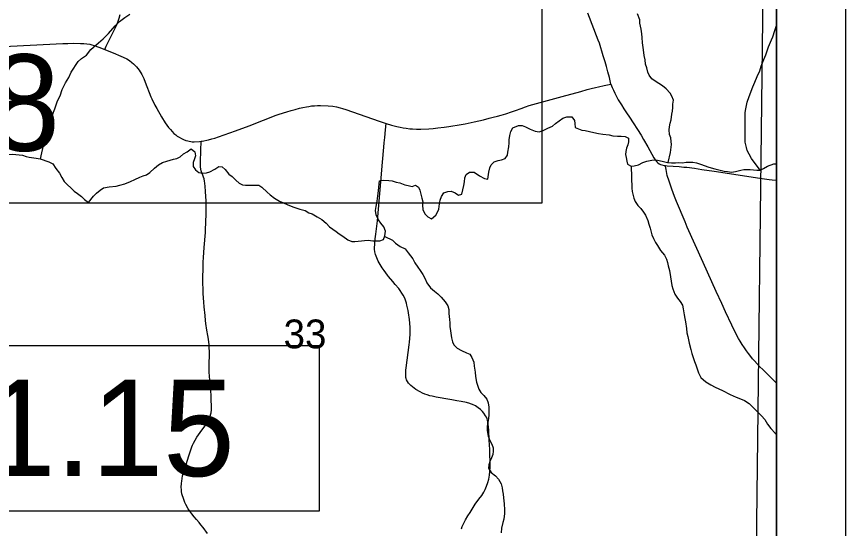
# Model space of a CAD drawing. Extents: x 0 to 34, y 0 to 22.
# Drawn here: x 24.295 to 25.5, y 16.628 to 17.371 of the extents above; entities that cross this region are included whole.
import ezdxf

# ---------------------------------------------------------------- set-up
doc = ezdxf.new("R2010")
doc.units = 0
for name, color, linetype in [('GM_X_Corporation', 7, 'Continuous'), ('GM_X_County_Road', 7, 'Continuous'), ('GM_X_Minor_River', 7, 'Continuous'), ('GM_X_Section_Text', 7, 'Continuous'), ('GM_X_Township_Road', 7, 'Continuous'), ('SH_Data', 7, 'Continuous'), ('SH_Text', 7, 'Continuous')]:
    doc.layers.add(name, color=color, linetype=linetype)

msp = doc.modelspace()

# ---------------------------------------------------------------- linework, layer by layer
at = {"layer": 'GM_X_Corporation'}
msp.add_lwpolyline([(25.4, 14.4307), (25.4, 19.0068), (24.5766, 19.0222), (24.3186, 19.0261), (24.3186, 19.1409), (24.169, 19.1418), (23.786, 19.1434), (23.5499, 19.1465), (23.3329, 19.1508), (22.6423, 19.1645), (21.8956, 19.1793), (21.7744, 19.1817), (21.5297, 19.1865), (21.2652, 19.1913), (20.8916, 19.1966), (20.254, 19.2058), (20.2471, 18.8539), (20.2208, 16.9558), (20.1987, 15.2691)], dxfattribs=at)
for points in [[(24.2765, 17.4936), (25.3807, 17.4896), (25.3688, 16.474), (24.2658, 16.4792), (24.2698, 16.6327)], [(25.4, 16.4736), (25.4, 17.4893), (25.3807, 17.4896), (25.3688, 16.474)]]:
    msp.add_lwpolyline(points, close=True, dxfattribs=at)
at = {"layer": 'GM_X_County_Road'}
for points in [[(25.1592, 17.2732), (25.158, 17.2779), (25.1569, 17.2826), (25.1547, 17.2912), (25.1526, 17.2989), (25.1507, 17.3055), (25.148, 17.3143), (25.1424, 17.3325), (25.1408, 17.3369), (25.1255, 17.3762)], [(24.2671, 17.3274), (24.3623, 17.332), (24.3697, 17.3322), (24.3776, 17.3325), (24.3882, 17.3323), (24.3932, 17.3321), (24.3971, 17.3316), (24.4017, 17.331), (24.4047, 17.3303), (24.4078, 17.3293), (24.415, 17.3267), (24.4233, 17.3233), (24.4392, 17.3171), (24.4432, 17.3154), (24.4503, 17.3124), (24.4553, 17.3098), (24.4594, 17.3073), (24.4626, 17.3047), (24.4653, 17.3024), (24.4676, 17.3003), (24.4695, 17.2983), (24.4714, 17.2959), (24.4733, 17.2933), (24.4773, 17.287), (24.4782, 17.2853), (24.48, 17.2812), (24.4821, 17.2759), (24.4902, 17.2549), (24.4917, 17.2517), (24.4962, 17.2424), (24.4989, 17.2375), (24.5058, 17.2258), (24.5113, 17.217), (24.5137, 17.2136), (24.5161, 17.2103), (24.519, 17.207), (24.5216, 17.2041), (24.524, 17.2016), (24.5265, 17.1994), (24.5288, 17.1977), (24.5316, 17.1959), (24.535, 17.1939), (24.5379, 17.1925), (24.541, 17.1914), (24.5441, 17.1906), (24.5503, 17.1895), (24.5531, 17.1893), (24.5612, 17.1897), (24.5635, 17.1901), (24.5649, 17.1903), (24.574, 17.1923), (24.5789, 17.1935), (24.5834, 17.1948), (24.5888, 17.1966), (24.6133, 17.2051), (24.6331, 17.2126), (24.6542, 17.2208), (24.6629, 17.2242), (24.6712, 17.2275), (24.6767, 17.2294), (24.6882, 17.2331), (24.6945, 17.235), (24.7, 17.2364), (24.7065, 17.238), (24.7114, 17.2392), (24.7166, 17.2401), (24.7202, 17.2408), (24.7241, 17.2414), (24.7281, 17.2418), (24.7325, 17.242), (24.7368, 17.2422), (24.7483, 17.2418), (24.755, 17.2409), (24.7602, 17.24), (24.7656, 17.2386), (24.7689, 17.2377), (24.7737, 17.2362), (24.8222, 17.2194), (24.8323, 17.216), (24.8402, 17.2137), (24.8478, 17.2117), (24.853, 17.2106), (24.8573, 17.2097), (24.8616, 17.209), (24.8667, 17.2084), (24.8707, 17.2081), (24.8763, 17.2078), (24.8827, 17.2077), (24.8943, 17.2081), (24.9008, 17.2086), (24.9077, 17.2094), (24.9167, 17.2105), (24.9236, 17.2115), (24.9291, 17.2124), (24.9354, 17.2134), (24.9474, 17.2156), (24.9603, 17.2183), (24.9737, 17.2214), (24.9821, 17.2235), (24.9881, 17.2249), (24.9941, 17.2264), (24.9995, 17.2279), (25.0064, 17.2301), (25.0146, 17.2329), (25.0205, 17.2349), (25.0286, 17.2379), (25.0348, 17.2401), (25.0401, 17.2419), (25.0455, 17.2437), (25.0882, 17.2551), (25.1153, 17.2626), (25.1247, 17.2652), (25.1305, 17.2667), (25.1366, 17.2682), (25.141, 17.2692), (25.1494, 17.271), (25.1592, 17.2732)], [(25.1592, 17.2732), (25.1611, 17.2684), (25.1627, 17.2645), (25.1647, 17.2601), (25.1672, 17.2553), (25.1699, 17.2501), (25.1743, 17.2431), (25.178, 17.2372), (25.1816, 17.2314), (25.186, 17.2249), (25.2029, 17.1988), (25.2067, 17.1926), (25.2127, 17.1822), (25.2217, 17.1661), (25.2236, 17.1629), (25.2257, 17.1602), (25.2271, 17.1588), (25.2294, 17.1572), (25.2313, 17.1564), (25.2329, 17.1558), (25.2367, 17.1549), (25.2385, 17.1547)], [(25.2385, 17.1547), (25.241, 17.1544), (25.2498, 17.1539), (25.2585, 17.1533), (25.2653, 17.1527), (25.2695, 17.1523), (25.2807, 17.1509), (25.2913, 17.1492), (25.3091, 17.1466), (25.3758, 17.1365), (25.3824, 17.1356), (25.3892, 17.1346), (25.3934, 17.1342), (25.4, 17.1338)], [(25.4, 16.8388), (25.3914, 16.8469), (25.3802, 16.8578), (25.375, 16.863), (25.3677, 16.871), (25.3651, 16.874), (25.3627, 16.8772), (25.3593, 16.8816), (25.3563, 16.8858), (25.3534, 16.8899), (25.3501, 16.8948), (25.3468, 16.8998), (25.3446, 16.9036), (25.3418, 16.9086), (25.3348, 16.9231), (25.3259, 16.9423), (25.3203, 16.9545), (25.3123, 16.9719), (25.2933, 17.0138), (25.2702, 17.0654), (25.2669, 17.0728), (25.2545, 17.1028), (25.2517, 17.1099), (25.2478, 17.1203), (25.2437, 17.1322), (25.241, 17.1406), (25.2404, 17.1433), (25.2392, 17.1493), (25.2386, 17.1538), (25.2385, 17.1547)]]:
    msp.add_lwpolyline(points, dxfattribs=at)
at = {"layer": 'GM_X_Minor_River'}
for points in [[(24.3298, 17.1643), (24.3311, 17.169), (24.3318, 17.1735), (24.3352, 17.1876), (24.3363, 17.1929), (24.3386, 17.2024), (24.342, 17.2134), (24.3431, 17.2184), (24.3465, 17.226), (24.3506, 17.2374), (24.3547, 17.2491), (24.3585, 17.256), (24.3615, 17.2651), (24.3664, 17.275), (24.371, 17.2826), (24.3747, 17.2906), (24.3849, 17.3058), (24.3898, 17.3103), (24.397, 17.3153), (24.4031, 17.3233), (24.4144, 17.3332), (24.4209, 17.3389), (24.4288, 17.3469), (24.4387, 17.3579), (24.4447, 17.364), (24.4527, 17.3701), (24.4599, 17.375)], [(25.2422, 17.1591), (25.2456, 17.1736), (25.2471, 17.1854), (25.2467, 17.19), (25.2463, 17.1949), (25.2444, 17.1998), (25.2436, 17.2067), (25.2444, 17.2112), (25.2451, 17.2165), (25.2466, 17.2215), (25.2477, 17.2295), (25.2485, 17.234), (25.2492, 17.239), (25.2492, 17.2439), (25.2499, 17.25), (25.2476, 17.2557), (25.2454, 17.2602), (25.2393, 17.2663), (25.2339, 17.2705), (25.2233, 17.2773), (25.2187, 17.2807), (25.2149, 17.286), (25.213, 17.2905), (25.2111, 17.2966), (25.2095, 17.3023), (25.2087, 17.3084), (25.2076, 17.3148), (25.2064, 17.3232), (25.2052, 17.3331), (25.2045, 17.3407), (25.2041, 17.3464), (25.2029, 17.3528), (25.2013, 17.3619), (25.201, 17.3665), (25.1979, 17.3752)], [(25.3761, 17.1481), (25.3637, 17.1651), (25.3603, 17.1715), (25.3572, 17.1765), (25.3561, 17.181), (25.3545, 17.189), (25.3541, 17.1977), (25.3545, 17.2027), (25.3544, 17.2179), (25.3541, 17.2228), (25.3544, 17.2319), (25.3551, 17.2372), (25.3574, 17.2467), (25.36, 17.2551), (25.3653, 17.2692), (25.3683, 17.276), (25.3717, 17.2844), (25.3755, 17.2923), (25.3777, 17.2992), (25.3815, 17.3087), (25.3841, 17.3159), (25.3882, 17.3273), (25.3924, 17.3376), (25.3946, 17.3421), (25.3973, 17.3512), (25.4, 17.3583)], [(24.8229, 17.1326), (24.8282, 17.1338), (24.8362, 17.133), (24.8411, 17.1327), (24.8472, 17.1308), (24.8521, 17.1296), (24.8597, 17.127), (24.8646, 17.1259), (24.87, 17.1244), (24.8749, 17.1263), (24.8795, 17.1236), (24.8814, 17.1191), (24.8829, 17.1134), (24.8845, 17.1073), (24.8856, 17.102), (24.8852, 17.0974), (24.8856, 17.091), (24.8887, 17.0849), (24.8929, 17.0803), (24.8982, 17.0773), (24.9047, 17.0826), (24.9088, 17.091), (24.9095, 17.0959), (24.911, 17.1043), (24.9129, 17.11), (24.9163, 17.1153), (24.922, 17.1172), (24.9269, 17.1176), (24.9326, 17.1153), (24.9376, 17.1116), (24.9425, 17.1131), (24.944, 17.1195), (24.9451, 17.1256), (24.9463, 17.1313), (24.947, 17.137), (24.9485, 17.1416), (24.9538, 17.1454), (24.9603, 17.145), (24.9682, 17.1397), (24.9755, 17.1359), (24.9804, 17.1352), (24.9815, 17.1451), (24.983, 17.1515), (24.9849, 17.1561), (24.9894, 17.1603), (24.9951, 17.1622), (25.0001, 17.1629), (25.0054, 17.1649), (25.0088, 17.1698), (25.0095, 17.1744), (25.0106, 17.182), (25.011, 17.1877), (25.0113, 17.1922), (25.0121, 17.1983), (25.0136, 17.2044), (25.0166, 17.2097), (25.0246, 17.2131), (25.0303, 17.2128), (25.0348, 17.2112), (25.0417, 17.2075), (25.0489, 17.2048), (25.055, 17.2037), (25.0607, 17.2056), (25.0675, 17.209), (25.0743, 17.2121), (25.0788, 17.2159), (25.0838, 17.2197), (25.0894, 17.2235), (25.0951, 17.2258), (25.1023, 17.2258), (25.1062, 17.2205), (25.1066, 17.2159), (25.1073, 17.2102), (25.1119, 17.208), (25.1168, 17.2064), (25.1218, 17.2057), (25.1282, 17.2042), (25.1343, 17.2027), (25.1411, 17.2015), (25.1472, 17.2004), (25.1567, 17.1993), (25.1617, 17.1982), (25.1685, 17.1974), (25.1742, 17.1974), (25.1799, 17.1971), (25.1845, 17.1948), (25.1849, 17.1895), (25.1837, 17.1849), (25.1818, 17.1803), (25.1807, 17.1754), (25.1804, 17.1708), (25.1811, 17.1663), (25.1823, 17.1614), (25.1834, 17.1568), (25.1884, 17.1538), (25.1929, 17.1542), (25.199, 17.1561), (25.2055, 17.1591), (25.2115, 17.1614), (25.2187, 17.1626), (25.2244, 17.1629)], [(24.1857, 17.2003), (24.1932, 17.1979), (24.1993, 17.1972), (24.2091, 17.1953), (24.2145, 17.1942), (24.2198, 17.1931), (24.2247, 17.1919), (24.2319, 17.1897), (24.2373, 17.1882), (24.2434, 17.184), (24.2483, 17.1794), (24.2567, 17.176), (24.2627, 17.1734), (24.2681, 17.1723), (24.2734, 17.1719), (24.2783, 17.1715), (24.2829, 17.1711), (24.2893, 17.1712), (24.2943, 17.1708), (24.2988, 17.1704), (24.3038, 17.1697), (24.3091, 17.1678), (24.3136, 17.167), (24.3239, 17.1655)], [(24.3239, 17.1655), (24.3296, 17.1644), (24.3421, 17.1602), (24.3478, 17.1572), (24.3524, 17.1504), (24.3574, 17.1436), (24.3612, 17.1375), (24.3646, 17.1318), (24.3791, 17.1174), (24.3837, 17.114), (24.3894, 17.1098), (24.394, 17.1053), (24.3997, 17.1011), (24.4072, 17.1102), (24.4114, 17.1148), (24.4167, 17.119), (24.4216, 17.1224), (24.4296, 17.1239), (24.4398, 17.1251), (24.4455, 17.1263), (24.4527, 17.1282), (24.4607, 17.1316), (24.4671, 17.1346), (24.4743, 17.1381), (24.4793, 17.14), (24.4842, 17.1415), (24.4891, 17.1449), (24.4959, 17.151), (24.5016, 17.156), (24.5073, 17.1594), (24.5137, 17.1613), (24.5232, 17.164), (24.5282, 17.1651), (24.5331, 17.1674), (24.538, 17.172), (24.5433, 17.1747), (24.549, 17.1789), (24.5543, 17.1747), (24.5551, 17.169), (24.5536, 17.1644), (24.5517, 17.1591), (24.5521, 17.1534), (24.5552, 17.1485), (24.5601, 17.1447), (24.5654, 17.1436), (24.5711, 17.144), (24.5761, 17.1455), (24.5836, 17.1497), (24.5893, 17.1535), (24.5939, 17.1531), (24.5984, 17.1489), (24.6038, 17.1425), (24.6087, 17.1387), (24.6137, 17.1338), (24.6186, 17.1292), (24.6236, 17.127), (24.6281, 17.1262), (24.6471, 17.1262), (24.6517, 17.1232), (24.6593, 17.116), (24.6639, 17.1122), (24.6703, 17.1073), (24.6776, 17.1031), (24.6833, 17.1005), (24.6897, 17.0978), (24.6981, 17.0944), (24.7068, 17.0914), (24.7148, 17.0895), (24.7198, 17.0861), (24.7247, 17.0846), (24.7323, 17.0801), (24.7388, 17.0763), (24.7452, 17.071), (24.7502, 17.0656), (24.7597, 17.0592), (24.7643, 17.0558), (24.7696, 17.0524), (24.7765, 17.0467), (24.7825, 17.0444), (24.7871, 17.0444), (24.7966, 17.0456), (24.8011, 17.046), (24.8065, 17.0464), (24.8129, 17.0456), (24.8186, 17.0453), (24.8232, 17.0456), (24.8285, 17.0476), (24.8307, 17.0529), (24.8315, 17.0593), (24.8292, 17.0658), (24.8246, 17.0711), (24.8215, 17.076), (24.8181, 17.0832), (24.8169, 17.0893), (24.8177, 17.0954), (24.8192, 17.103), (24.8203, 17.111), (24.8214, 17.1182), (24.8218, 17.1235), (24.8221, 17.1281), (24.8229, 17.1326)], [(25.2244, 17.1629), (25.2294, 17.1622), (25.2354, 17.1607), (25.2415, 17.1592), (25.2472, 17.1588), (25.2529, 17.1588), (25.2578, 17.1592), (25.2632, 17.1588), (25.2685, 17.1596), (25.278, 17.1596), (25.2833, 17.1589), (25.2909, 17.1562), (25.3, 17.1532), (25.3049, 17.1517), (25.3103, 17.1502), (25.3179, 17.1483), (25.3236, 17.1468), (25.3285, 17.146), (25.3342, 17.1453), (25.3403, 17.1464), (25.3479, 17.148), (25.3524, 17.1491), (25.3615, 17.1491), (25.3664, 17.1487), (25.371, 17.148), (25.3759, 17.148), (25.3809, 17.1503), (25.3866, 17.1537), (25.3957, 17.1575), (25.4, 17.1571)], [(25.1884, 17.1538), (25.1893, 17.1219), (25.19, 17.1173), (25.1923, 17.1074), (25.1943, 17.1025), (25.1981, 17.0968), (25.2026, 17.0926), (25.2065, 17.0873), (25.2095, 17.0828), (25.2129, 17.0752), (25.2141, 17.0695), (25.216, 17.0638), (25.2187, 17.0543), (25.221, 17.049), (25.2241, 17.0429), (25.2267, 17.0384), (25.2313, 17.0315), (25.237, 17.0247), (25.2401, 17.0186), (25.2416, 17.0141), (25.2424, 17.0091), (25.2443, 17.0023), (25.2455, 16.9932), (25.2478, 16.9803), (25.249, 16.9757), (25.252, 16.9681), (25.2558, 16.9621), (25.2597, 16.9571), (25.2631, 16.9518), (25.2642, 16.9465), (25.2658, 16.9381), (25.2666, 16.9325), (25.2673, 16.9279), (25.2689, 16.918), (25.2697, 16.9119), (25.2708, 16.9066), (25.272, 16.9017), (25.2728, 16.8968), (25.2751, 16.8876), (25.2766, 16.8819), (25.2785, 16.8759), (25.2808, 16.8702), (25.2824, 16.8652), (25.2843, 16.8592), (25.2862, 16.8535), (25.2896, 16.847), (25.2972, 16.8406), (25.3045, 16.8364), (25.3105, 16.8326), (25.3212, 16.8277), (25.3326, 16.822), (25.3413, 16.8182), (25.3474, 16.8156), (25.3535, 16.8133), (25.36, 16.8088), (25.3645, 16.8046), (25.371, 16.7981), (25.3779, 16.7909), (25.3828, 16.7856), (25.3866, 16.7792), (25.3916, 16.7727), (25.3981, 16.7659), (25.4, 16.7647)], [(24.8303, 17.0519), (24.8414, 17.0464), (24.846, 17.0419), (24.8528, 17.0373), (24.86, 17.0336), (24.8646, 17.0279), (24.8711, 17.0191), (24.8741, 17.0135), (24.8783, 17.007), (24.8818, 17.0025), (24.8856, 16.9964), (24.889, 16.9903), (24.8917, 16.9842), (24.897, 16.977), (24.9027, 16.9721), (24.9073, 16.9683), (24.9126, 16.9634), (24.918, 16.9566), (24.9222, 16.9512), (24.9233, 16.9455), (24.9237, 16.9398), (24.9245, 16.9311), (24.9249, 16.9262), (24.9249, 16.9209), (24.9257, 16.9144), (24.9273, 16.9045), (24.9288, 16.8988), (24.9307, 16.8943), (24.9357, 16.8893), (24.9418, 16.8859), (24.9494, 16.8825), (24.9539, 16.8806), (24.957, 16.8761), (24.9597, 16.8689), (24.9604, 16.8632), (24.9616, 16.8548), (24.9624, 16.8484), (24.9639, 16.84), (24.9658, 16.8343), (24.967, 16.8298), (24.9701, 16.8248), (24.9746, 16.8207), (24.9788, 16.8153), (24.9807, 16.81), (24.9815, 16.8036), (24.9815, 16.7926), (24.9812, 16.7872), (24.9804, 16.7812), (24.9793, 16.7762), (24.9793, 16.7698), (24.9809, 16.7618), (24.9832, 16.7553), (24.9859, 16.75), (24.9878, 16.7447), (24.9882, 16.7398), (24.9874, 16.7348), (24.9855, 16.7299), (24.9829, 16.7249), (24.9818, 16.72), (24.9814, 16.7151), (24.9849, 16.709), (24.9913, 16.7041), (24.9959, 16.6991), (24.9997, 16.6923), (25.0012, 16.6866), (25.0016, 16.682), (25.0024, 16.6771), (25.0032, 16.6718), (25.004, 16.6631), (25.0044, 16.6547), (25.0044, 16.6494), (25.0037, 16.641), (25.0018, 16.6361), (25.0003, 16.6281), (24.9996, 16.6213)]]:
    msp.add_lwpolyline(points, dxfattribs=at)
at = {"layer": 'GM_X_Township_Road'}
for points in [[(24.4233, 17.3233), (24.4255, 17.3282), (24.4322, 17.342), (24.4372, 17.3518), (24.4389, 17.3554), (24.4415, 17.3609), (24.4427, 17.3646), (24.4442, 17.369), (24.4457, 17.3741)], [(24.9551, 16.8086), (24.9542, 16.809), (24.9491, 16.8103), (24.9415, 16.8118), (24.9353, 16.813), (24.9277, 16.8144), (24.9191, 16.8159), (24.9111, 16.8173), (24.9053, 16.8184), (24.8993, 16.8195), (24.8959, 16.8203), (24.8922, 16.8215), (24.8887, 16.8227), (24.8851, 16.8242), (24.8819, 16.8258), (24.8757, 16.8294), (24.8732, 16.8311), (24.8681, 16.8351), (24.8667, 16.8365), (24.8648, 16.8387), (24.8633, 16.8411), (24.8621, 16.8435), (24.8615, 16.8452), (24.8611, 16.847), (24.8608, 16.8492), (24.8612, 16.8576), (24.8617, 16.8611), (24.8661, 16.8943), (24.8664, 16.8981), (24.8671, 16.9092), (24.8672, 16.9126), (24.8671, 16.92), (24.8662, 16.9313), (24.865, 16.9408), (24.8644, 16.944), (24.8627, 16.9518), (24.8619, 16.9547), (24.8599, 16.9605), (24.8589, 16.9629), (24.8572, 16.9663), (24.8553, 16.9695), (24.853, 16.9731), (24.8507, 16.9762), (24.8457, 16.9822), (24.8423, 16.9861), (24.8359, 16.9934), (24.8343, 16.9956), (24.8297, 17.0021), (24.8265, 17.0064), (24.8238, 17.0108), (24.8209, 17.0161), (24.8188, 17.0206), (24.8171, 17.0256), (24.8161, 17.0294), (24.8156, 17.0332), (24.8158, 17.0426), (24.8162, 17.0482), (24.8172, 17.0552), (24.8184, 17.0631), (24.8196, 17.0747), (24.8245, 17.1312), (24.827, 17.1596), (24.829, 17.1816), (24.8295, 17.1877), (24.8303, 17.1958), (24.8313, 17.2066), (24.8323, 17.216)], [(24.5626, 17.1576), (24.5627, 17.1604), (24.563, 17.1768), (24.5635, 17.1901)], [(24.5729, 16.6203), (24.5664, 16.6289), (24.5632, 16.6328), (24.5604, 16.636), (24.5565, 16.6406), (24.5533, 16.6444), (24.5498, 16.6488), (24.5471, 16.6525), (24.5448, 16.6561), (24.5413, 16.6624), (24.54, 16.6651), (24.5372, 16.6722), (24.5364, 16.6749), (24.5356, 16.6779), (24.5351, 16.6811), (24.5348, 16.6839), (24.5346, 16.6871), (24.5349, 16.6935), (24.5352, 16.696), (24.5357, 16.7002), (24.5366, 16.7037), (24.5373, 16.7068), (24.5386, 16.7114), (24.5416, 16.7206), (24.5457, 16.7332), (24.5501, 16.7462), (24.551, 16.7483), (24.5525, 16.7516), (24.5548, 16.7559), (24.5573, 16.7599), (24.5646, 16.7702), (24.5678, 16.7747), (24.5725, 16.7813), (24.5741, 16.784), (24.5756, 16.787), (24.5764, 16.7892), (24.5773, 16.7924), (24.578, 16.7957), (24.5784, 16.7998), (24.5786, 16.8041), (24.5782, 16.8154), (24.5779, 16.8218), (24.5775, 16.8267), (24.5765, 16.8371), (24.575, 16.8544), (24.5749, 16.8577), (24.575, 16.8685), (24.5755, 16.8778), (24.5756, 16.8832), (24.5753, 16.8913), (24.5751, 16.8943), (24.574, 16.9027), (24.573, 16.908), (24.5718, 16.9158), (24.5704, 16.9252), (24.57, 16.9296), (24.5694, 16.9367), (24.568, 16.9496), (24.5673, 16.9562), (24.5668, 16.9628), (24.5665, 16.9688), (24.5664, 16.9718), (24.5662, 16.9762), (24.5661, 16.983), (24.5663, 17.0144), (24.5667, 17.0213), (24.5678, 17.0357), (24.5696, 17.0575), (24.5698, 17.0611), (24.5707, 17.0849), (24.5708, 17.093), (24.5707, 17.1038), (24.5705, 17.1092), (24.5699, 17.1178), (24.5694, 17.1245), (24.569, 17.1292), (24.5685, 17.1322), (24.5678, 17.1355), (24.5669, 17.1379), (24.5658, 17.1407), (24.5639, 17.1457), (24.5635, 17.1473), (24.5626, 17.1524), (24.5625, 17.1543), (24.5626, 17.1567), (24.5626, 17.1576)], [(24.9417, 16.6268), (24.943, 16.6304), (24.9444, 16.6334), (24.9479, 16.6398), (24.9513, 16.6457), (24.9543, 16.6508), (24.9572, 16.6556), (24.9619, 16.6627), (24.9672, 16.6698), (24.9713, 16.6752), (24.973, 16.6776), (24.9744, 16.6803), (24.9764, 16.6842), (24.9783, 16.6888), (24.9802, 16.694), (24.9815, 16.6993), (24.9825, 16.7049), (24.983, 16.7102), (24.9835, 16.7169), (24.983, 16.7424), (24.9823, 16.7556), (24.9815, 16.7704), (24.9812, 16.7752), (24.9808, 16.7785), (24.9804, 16.7818), (24.9799, 16.7846), (24.9792, 16.7869), (24.9782, 16.7892), (24.977, 16.7913), (24.9744, 16.795), (24.9724, 16.7975), (24.9694, 16.8004), (24.9661, 16.8029), (24.9621, 16.8055), (24.9579, 16.8075), (24.9551, 16.8086)]]:
    msp.add_lwpolyline(points, dxfattribs=at)
at = {"layer": 'SH_Data'}
for points in [[(18.5, 20.5), (25.5, 20.5), (25.5, 13.5), (18.5, 13.5)], [(18.6, 20.4), (25.4, 20.4), (25.4, 13.6), (18.6, 13.6)]]:
    msp.add_lwpolyline(points, close=True, dxfattribs=at)
at = {"layer": 'SH_Text'}
for points in [[(23.3613, 17.8253), (25.0586, 17.8253), (25.0586, 17.1004), (23.3613, 17.1004)], [(23.3742, 16.893), (23.3742, 16.653), (24.7353, 16.653), (24.7353, 16.893)]]:
    msp.add_lwpolyline(points, close=True, dxfattribs=at)

# ---------------------------------------------------------------- texts
at = {"layer": 'GM_X_Section_Text'}
msp.add_text('33', height=0.04186, rotation=0, dxfattribs=at).set_placement((24.6833, 16.8892))
at = {"layer": 'SH_Text'}
for s, p in [('S.L.M. 1.18', (23.4011, 17.1763)), ('HAS-646-1.15', (23.426, 16.7035))]:
    msp.add_text(s, height=0.14, dxfattribs=at).set_placement(p)

doc.saveas('drawing.dxf')
